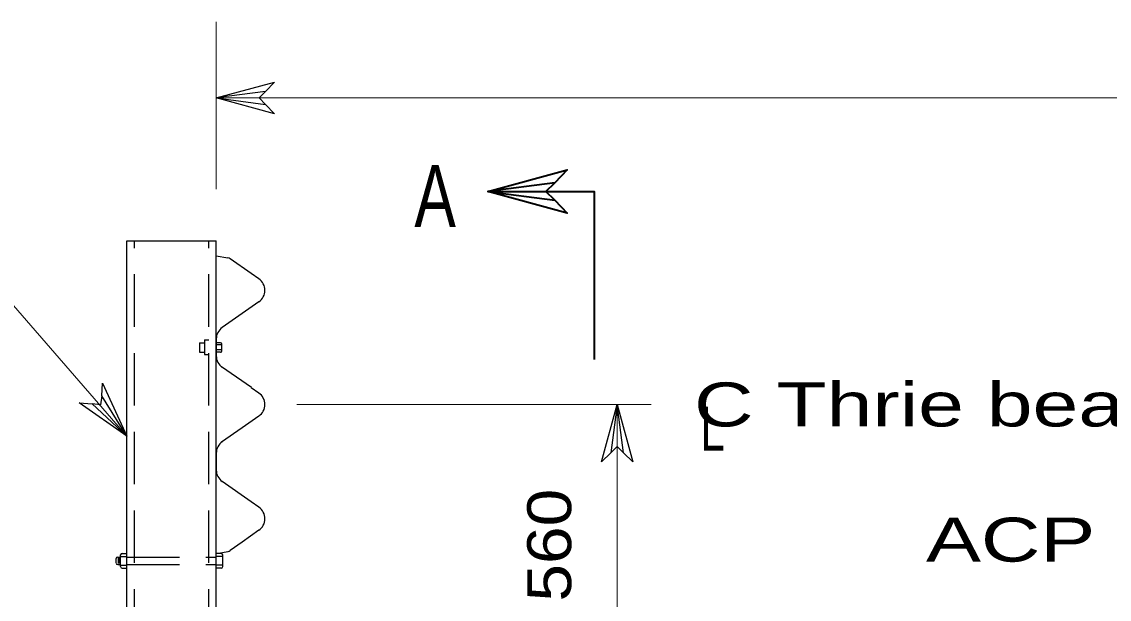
# Model space of a CAD drawing. Extents: x 13426 to 15509, y -9298 to -5111.
# Drawn here: x 15341.75 to 15374.08, y -5497.78 to -5480.61 of the extents above; entities that cross this region are included whole.
import ezdxf
from ezdxf.enums import TextEntityAlignment as Align

# ---------------------------------------------------------------- set-up
doc = ezdxf.new("R2010")
doc.units = 0
doc.header["$LTSCALE"] = 0.52
doc.linetypes.add('MEDIUM_DASHED', pattern=[4.5, 3, -1.5])
for name, color, linetype, lineweight in [('1', 7, 'Continuous', 13), ('15', 7, 'Continuous', 13), ('16', 7, 'Continuous', 25), ('20', 7, 'Continuous', 13), ('3', 7, 'Continuous', 25), ('4', 7, 'Continuous', 13), ('5', 7, 'Continuous', 25)]:
    doc.layers.add(name, color=color, linetype=linetype, lineweight=lineweight)
doc.layers.add('19', color=7, linetype='Continuous')

msp = doc.modelspace()

# ---------------------------------------------------------------- linework, layer by layer
at = {"layer": '1'}
for p, q in [((15347.53, -5480.613), (15347.53, -5485.587)), ((15412.258, -5482.878), (15347.53, -5482.878))]:
    msp.add_line(p, q, dxfattribs=at)
at = {"layer": '1', "lineweight": 25}
for p, q in [((15347.53, -5487.565), (15347.878, -5487.626)), ((15348.569, -5488.094), (15347.945, -5487.655)), ((15348.799, -5488.252), (15348.57, -5488.092)), ((15348.799, -5488.939), (15348.296, -5489.286)), ((15348.296, -5489.287), (15347.708, -5489.7)), ((15347.53, -5490.546), (15347.53, -5490.043)), ((15347.53, -5490.043), (15347.53, -5490.546)), ((15348.573, -5491.487), (15347.684, -5490.873)), ((15348.799, -5491.65), (15348.57, -5491.491)), ((15348.799, -5492.333), (15348.297, -5492.684)), ((15348.296, -5492.682), (15347.684, -5493.11)), ((15347.53, -5493.434), (15347.53, -5493.933)), ((15347.53, -5493.933), (15347.53, -5493.434)), ((15348.799, -5495.726), (15348.296, -5496.078)), ((15348.296, -5496.077), (15347.945, -5496.326)), ((15347.532, -5496.413), (15347.879, -5496.354))]:
    msp.add_line(p, q, dxfattribs=at)
msp.add_lwpolyline([(15348.799, -5495.043), (15348.57, -5494.884), (15347.708, -5494.281)], dxfattribs=at)
for centre, radius, start, end in [((15347.8471, -5487.7915), 0.1669, 55.00074, 79.99915), ((15348.5586, -5488.5954), 0.4173, 304.98447, 55.01608), ((15347.9465, -5490.0422), 0.4173, 124.98447, 180.00047), ((15347.9465, -5490.543), 0.4173, 179.99952, 235.01552), ((15348.5586, -5491.9897), 0.4173, 304.98447, 55.01608), ((15348.5586, -5491.9898), 0.4173, 304.98394, 55.01555), ((15347.9465, -5493.4365), 0.4173, 124.98453, 180.00053), ((15347.9465, -5493.9373), 0.4173, 179.99957, 235.01557), ((15348.5586, -5495.3841), 0.4173, 304.98394, 55.01555), ((15347.8494, -5496.1891), 0.1669, 280.00088, 304.99929)]:
    msp.add_arc(centre, radius, start, end, dxfattribs=at)
at = {"layer": '15'}
for p, q in [((15338.505, -5485.608), (15344.875, -5492.929)), ((15359.445, -5491.991), (15359.445, -5501.728))]:
    msp.add_line(p, q, dxfattribs=at)
at = {"layer": '15', "linetype": 'MEDIUM_DASHED', "lineweight": 25}
for p, q in [((15347.035, -5490.156), (15347.177, -5490.156)), ((15347.035, -5490.433), (15347.177, -5490.433))]:
    msp.add_line(p, q, dxfattribs=at)
at = {"layer": '15', "lineweight": 25}
for p, q in [((15347.655, -5490.156), (15347.53, -5490.156)), ((15347.699, -5490.218), (15347.53, -5490.218)), ((15347.699, -5490.368), (15347.53, -5490.368)), ((15347.655, -5490.433), (15347.53, -5490.433))]:
    msp.add_line(p, q, dxfattribs=at)
at = {"layer": '15', "lineweight": 35}
msp.add_lwpolyline([(15355.601, -5485.658), (15358.759, -5485.658), (15358.759, -5490.654)], dxfattribs=at)
at = {"layer": '16'}
for points in [[(15348.995, -5483.069), (15349.265, -5483.351), (15347.53, -5482.878), (15349.265, -5482.405), (15348.995, -5482.687), (15347.53, -5482.878), (15348.995, -5483.069), (15348.803, -5482.878), (15348.995, -5482.687)], [(15344.127, -5491.731), (15344.152, -5491.356), (15344.875, -5492.929), (15343.457, -5491.939), (15343.843, -5491.966), (15344.875, -5492.929), (15344.127, -5491.731), (15344.084, -5491.995), (15343.843, -5491.966)], [(15359.257, -5493.429), (15358.98, -5493.695), (15359.445, -5491.991), (15359.91, -5493.695), (15359.633, -5493.429), (15359.445, -5491.991), (15359.257, -5493.429), (15359.445, -5493.241), (15359.633, -5493.429)]]:
    msp.add_lwpolyline(points, dxfattribs=at)
at = {"layer": '16', "lineweight": 35}
msp.add_lwpolyline([(15357.592, -5485.918), (15357.959, -5486.301), (15355.601, -5485.658), (15357.959, -5485.015), (15357.592, -5485.398), (15355.601, -5485.658), (15357.592, -5485.918), (15357.332, -5485.658), (15357.592, -5485.398)], dxfattribs=at)
at = {"layer": '3', "linetype": 'MEDIUM_DASHED'}
for p, q in [((15347.035, -5490.156), (15347.035, -5490.433)), ((15347.177, -5490.07), (15347.177, -5490.507)), ((15347.177, -5490.07), (15347.309, -5490.07)), ((15347.177, -5490.507), (15347.309, -5490.507)), ((15344.875, -5496.522), (15347.53, -5496.522)), ((15344.875, -5496.744), (15347.53, -5496.744))]:
    msp.add_line(p, q, dxfattribs=at)
at = {"layer": '3'}
for p, q in [((15347.699, -5490.388), (15347.699, -5490.2)), ((15344.555, -5496.699), (15344.555, -5496.566)), ((15344.6, -5496.522), (15344.684, -5496.522)), ((15344.61, -5496.554), (15344.61, -5496.714)), ((15344.656, -5496.554), (15344.656, -5496.714)), ((15344.685, -5496.807), (15344.685, -5496.458)), ((15344.685, -5496.51), (15344.876, -5496.51)), ((15344.729, -5496.414), (15344.874, -5496.414)), ((15347.721, -5496.51), (15347.53, -5496.51)), ((15347.677, -5496.414), (15347.532, -5496.414)), ((15347.721, -5496.807), (15347.721, -5496.458)), ((15344.6, -5496.744), (15344.684, -5496.744)), ((15344.685, -5496.759), (15344.876, -5496.759)), ((15344.729, -5496.851), (15344.874, -5496.851)), ((15347.721, -5496.759), (15347.53, -5496.759)), ((15347.677, -5496.851), (15347.532, -5496.851))]:
    msp.add_line(p, q, dxfattribs=at)
for centre, start, end in [((15347.6547, -5490.2002), 0, 90), ((15347.6547, -5490.3882), 269.99997, 0), ((15344.5998, -5496.5666), 90, 180), ((15344.7292, -5496.4581), 90, 180), ((15347.6768, -5496.4581), 0, 90), ((15344.5998, -5496.6994), 180, 269.99999), ((15344.7292, -5496.8073), 180, 269.99999), ((15347.6768, -5496.8073), 270, 0)]:
    msp.add_arc(centre, 0.0443, start, end, dxfattribs=at)
at = {"layer": '4'}
msp.add_line((15349.929, -5491.991), (15360.455, -5491.991), dxfattribs=at)
at = {"layer": '5', "linetype": 'MEDIUM_DASHED'}
for p, q in [((15345.096, -5503.719), (15345.096, -5487.122)), ((15347.309, -5503.719), (15347.309, -5487.122))]:
    msp.add_line(p, q, dxfattribs=at)
at = {"layer": '5'}
for points in [[(15344.875, -5503.719), (15344.875, -5487.122), (15347.53, -5487.122)], [(15347.862, -5503.719), (15347.53, -5503.719), (15347.53, -5487.122)]]:
    msp.add_lwpolyline(points, dxfattribs=at)

# ---------------------------------------------------------------- texts
at = {"layer": '19', "width": 1.15}
msp.add_text('560', height=1.307, rotation=90, dxfattribs=at).set_placement((15358.081, -5496.17), align=Align.CENTER)
at = {"layer": '20'}
for s, height, width, p in [('A', 1.844, 0.75, (15354.036, -5486.713)), ('C Thrie beam', 1.307, 1.4, (15369.145, -5492.641)), ('L', 1.307, 0.75, (15362.282, -5493.36)), ('ACP overlay (see Note 8)', 1.307, 1.4, (15382.5005, -5496.658))]:
    msp.add_text(s, height=height, dxfattribs=dict(at, width=width)).set_placement(p, align=Align.CENTER)

doc.saveas('drawing.dxf')
